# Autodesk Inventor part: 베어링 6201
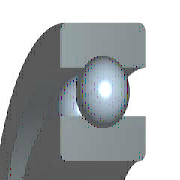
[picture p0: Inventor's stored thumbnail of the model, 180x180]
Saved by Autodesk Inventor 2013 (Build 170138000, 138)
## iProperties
IsCustomPart: 1
Created: 2012-02
Part Number: 베어링 6201
Material: 강철, 연강
Description: 깊은 그루브 볼 베어링
Document SubType Name: Modeling
Standard: KS B 2023
Designer: test
Standards Organization: KS
Language: ko-KR
Size Designation: 6201 - 12 x 32 x 10
Categories: <MemberInstance><Categories><Category DisplayName="샤프트 부품" InternalName="7f7aeb1f-a693-4053-b835-cee3144e0d98" Mnemonic="SHFT"><Category DisplayName="베어링" Inter
Density: 1 g/cm^3
Author: test
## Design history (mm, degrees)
sketch "스케치" dims "d0" = 5.2 (= -0.26 x WD + 0.26 x BD)
  geometry: L1 (2.4, 11)-(7.6, 11); L2 (5, 11)-(5, 8.4); L3 (5, 11)-(5, 13.6); L4 (3.068, 9.26)-(0, 9.26); L5 (0, 6)-(10, 6); L6 (3.068, 12.74)-(0, 12.74); L7 (0, 16)-(10, 16); L8 (10, 6)-(10, 9.26); L9 (6.932, 9.26)-(10, 9.26); L10 (6.932, 12.74)-(10, 12.74); L11 (10, 16)-(10, 12.74); L12 (-1.4, 0)-(8.4, 0) reference; L13 (0, -0.3)-(0, 5.3) reference
  constraints: 22 end point, 4 point on line, 2 collinear, 2 perpendicular, 2 symmetric about line, 1 midpoint, 1 parallel, 14 other
  dimensions: "d9" = 12 diameter of L5 L12 (= WD); "d11" = 32 diameter of L7 L12 (= BD); "d12" = 10 distance between parallel lines of L8 L13 (= KB); "d13" = 18.52 diameter of L9 L12 (= 0.326 x BD + 0.674 x WD)
revolve "본체" stored, may be unused: angle "d6" = 90 deg
revolve "볼" stored, may be unused: angle "d7" = 90 deg
pattern_circular "IDS_ARRAYBALL[SIMPL:T]" dims angle "d3" = 360 deg
body "Solid1"
fillet "모깎기1" dims "d1" = 0.6 (= KRS)
other parameters: "WD" = 12 [user parameter; used in 5 equation terms], "BD" = 32 [user parameter; used in 5 equation terms], "KB" = 10 [user parameter; used in 1 equation term], "KRS" = 0.6 [user parameter; used in 1 equation term], "d4" = 0, "d5" = 0, "d8" = 0, "d14" = 0, "d15" = 0, "BBA" = 0 [user parameter], "BC0" = 3100000 [user parameter], "BC" = 6890000 [user parameter], "BR" = 16 (= 0.5 x BD) [user parameter], "WR" = 6 (= 0.5 x WD) [user parameter]
